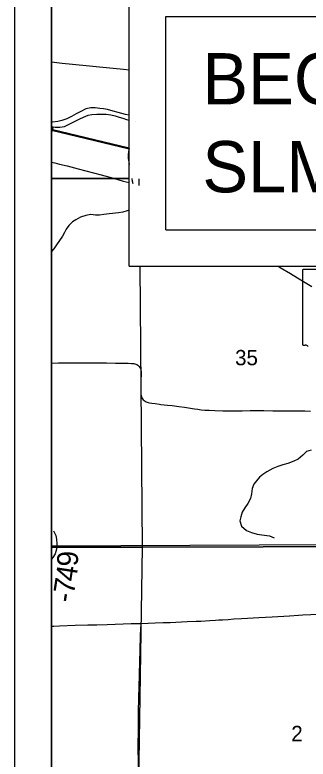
# Model space of a CAD drawing. Extents: x 0 to 34, y 0 to 22.
# Drawn here: x 1.76 to 2.561, y 16.14 to 18.172 of the extents above; entities that cross this region are included whole.
import ezdxf

# ---------------------------------------------------------------- set-up
doc = ezdxf.new("R2010")
doc.units = 0
for name, color, linetype in [('GM_X_County_Road', 7, 'Continuous'), ('GM_X_County_Road_Text', 7, 'Continuous'), ('GM_X_County_Text', 7, 'Continuous'), ('GM_X_Interchange_Ramps', 7, 'Continuous'), ('GM_X_Major_River_Text', 7, 'Continuous'), ('GM_X_State_Location', 7, 'Continuous'), ('GM_X_State_Route', 7, 'Continuous'), ('GM_X_State_Shield', 7, 'Continuous'), ('GM_X_Township_Road', 7, 'Continuous'), ('GM_X_Township_Text', 7, 'Continuous'), ('SH_Data', 7, 'Continuous'), ('SH_Text', 7, 'Continuous')]:
    doc.layers.add(name, color=color, linetype=linetype)

msp = doc.modelspace()

# ---------------------------------------------------------------- linework, layer by layer
at = {"layer": 'GM_X_County_Road'}
for p, q in [((2.6247, 17.4771), (2.5475, 17.4771)), ((2.5449, 17.4737), (2.5449, 17.2736))]:
    msp.add_line(p, q, dxfattribs=at)
for points in [[(1.8602, 17.7701), (1.8605, 17.77), (1.8696, 17.7677), (1.8816, 17.7646), (1.9027, 17.7595), (1.9328, 17.7516), (1.9748, 17.7406), (1.9958, 17.7349), (2.029, 17.7258), (2.0556, 17.7184), (2.0719, 17.7141)], [(2.4795, 17.4855), (2.4808, 17.4847), (2.4847, 17.4824), (2.5127, 17.4656), (2.5313, 17.4544), (2.5525, 17.4416), (2.5711, 17.4302)]]:
    msp.add_lwpolyline(points, dxfattribs=at)
for centre, radius, start, end in [((2.5479, 17.4741), 0.00305, 98.1301, 188.1301), ((2.5479, 17.2731), 0.00308, 171.9584, 258.3066), ((2.5484, 17.2936), 0.0235, 267.339, 280.6039), ((2.5532, 17.262), 0.00848, 29.7484, 93.2717)]:
    msp.add_arc(centre, radius, start, end, dxfattribs=at)
at = {"layer": 'GM_X_County_Road_Text'}
msp.add_line((2.0901, 17.8819), (2.0901, 17.8819), dxfattribs=at)
for points in [[(1.8644, 17.8663), (1.8622, 17.8575), (1.8602, 17.8514)], [(2.0719, 17.807), (2.0706, 17.7993), (2.0694, 17.7895), (2.0694, 17.78), (2.0709, 17.7705), (2.0719, 17.7633)], [(2.0792, 17.7249), (2.0807, 17.7177), (2.0826, 17.7112)], [(2.0719, 17.6391), (2.0666, 17.6368), (2.0548, 17.6334), (2.043, 17.6319), (2.0271, 17.63), (2.0172, 17.6285), (2.0032, 17.6266), (1.991, 17.6251), (1.98, 17.6255), (1.9675, 17.6266), (1.9542, 17.6243), (1.9394, 17.6198), (1.9269, 17.6126), (1.9174, 17.6069), (1.9079, 17.597), (1.9006, 17.5871), (1.8957, 17.5776), (1.8904, 17.5682), (1.8816, 17.5556), (1.874, 17.5442), (1.8664, 17.5336), (1.8602, 17.5259)], [(2.5688, 16.9838), (2.5559, 16.98), (2.546, 16.9698), (2.5338, 16.9591), (2.5213, 16.9535), (2.505, 16.947), (2.4917, 16.9436), (2.4776, 16.9387), (2.464, 16.9337), (2.4476, 16.9246), (2.4374, 16.9174), (2.4279, 16.9094), (2.4195, 16.9), (2.4123, 16.8905), (2.4077, 16.8791), (2.4062, 16.8643), (2.4031, 16.8514), (2.3963, 16.8381), (2.3883, 16.8263), (2.3803, 16.8142), (2.3769, 16.8016), (2.3746, 16.791), (2.3791, 16.7762), (2.392, 16.7644), (2.4057, 16.7583), (2.4212, 16.7538), (2.4345, 16.7522), (2.455, 16.7492), (2.4683, 16.7446)], [(1.8655, 16.7631), (1.8724, 16.7502), (1.8742, 16.7403), (1.8746, 16.7274), (1.8738, 16.713), (1.87, 16.7009), (1.8639, 16.6906), (1.8602, 16.6861)]]:
    msp.add_lwpolyline(points, dxfattribs=at)
at = {"layer": 'GM_X_County_Text'}
for p, q in [((1.8602, 17.8597), (2.0719, 17.8086)), ((1.8602, 17.8573), (2.0719, 17.8062))]:
    msp.add_line(p, q, dxfattribs=at)
at = {"layer": 'GM_X_Interchange_Ramps'}
for points in [[(1.8602, 17.2215), (1.8797, 17.2217), (1.8921, 17.2218), (1.9139, 17.222), (1.9356, 17.2221), (1.9667, 17.222), (1.9884, 17.222), (2.0101, 17.2217), (2.035, 17.2213), (2.0536, 17.2212), (2.0691, 17.2209), (2.0784, 17.2206), (2.0845, 17.22), (2.0875, 17.2194), (2.0903, 17.2185), (2.093, 17.2173), (2.0955, 17.2158), (2.0978, 17.2139), (2.0998, 17.2117), (2.1015, 17.2093), (2.1028, 17.2066), (2.1038, 17.2038), (2.1043, 17.2007), (2.1046, 17.1979), (2.1047, 17.1944), (2.1047, 17.1911), (2.1044, 17.1753), (2.1037, 17.1448), (2.1039, 17.139), (2.1039, 17.1358), (2.1046, 17.1325), (2.1054, 17.1288), (2.1068, 17.1264), (2.1084, 17.1236), (2.1104, 17.121), (2.1128, 17.1188), (2.1155, 17.1171), (2.1184, 17.1157), (2.1214, 17.1146), (2.1244, 17.1137), (2.1275, 17.113), (2.1337, 17.112), (2.1429, 17.1108), (2.1552, 17.1089), (2.159, 17.1084)], [(2.159, 17.1084), (2.1675, 17.1073), (2.1768, 17.1063), (2.1891, 17.1051), (2.2076, 17.1029), (2.223, 17.1009), (2.2506, 17.0965), (2.2598, 17.0952), (2.269, 17.094), (2.2783, 17.0931), (2.2907, 17.0923), (2.3062, 17.0918), (2.3279, 17.0912), (2.3434, 17.0908), (2.3527, 17.0906), (2.3652, 17.0908), (2.3807, 17.0911), (2.4024, 17.0916), (2.4148, 17.0918), (2.4397, 17.0916), (2.4645, 17.0912), (2.4894, 17.0912), (2.5049, 17.0912), (2.5359, 17.0909), (2.5514, 17.0907), (2.5669, 17.0902)], [(2.0973, 16.1065), (2.0974, 16.1168), (2.0972, 16.1385), (2.0969, 16.1634), (2.0969, 16.1852), (2.0972, 16.2101), (2.0976, 16.2381), (2.0979, 16.263), (2.0988, 16.3128), (2.0993, 16.3315), (2.0995, 16.3439), (2.1, 16.3625), (2.1006, 16.381), (2.1012, 16.3965), (2.1017, 16.4121), (2.1021, 16.4308), (2.1024, 16.4463), (2.1028, 16.468), (2.1031, 16.4804), (2.1037, 16.4929), (2.1045, 16.5107)]]:
    msp.add_lwpolyline(points, dxfattribs=at)
at = {"layer": 'GM_X_State_Route'}
msp.add_line((2.0999, 17.7064), (2.0998, 17.7248), dxfattribs=at)
for points in [[(2.0795, 18.2679), (2.0616, 18.746), (1.8602, 18.7459), (1.8602, 17.7252), (2.0719, 17.7249)], [(2.0719, 17.7249), (1.8602, 17.7252), (1.8602, 16.7185), (2.1086, 16.7183), (2.1019, 17.4855)], [(3.0896, 17.4855), (3.0962, 16.7214), (2.1086, 16.7183), (2.1019, 17.4855)], [(4.1201, 16.507), (4.1149, 16.7255), (3.8667, 16.7261), (3.8624, 16.726), (3.8538, 16.7259), (3.7775, 16.7251), (3.6944, 16.7259), (3.6091, 16.7254), (3.5492, 16.7252), (3.5064, 16.7242), (3.4642, 16.7247), (3.3781, 16.7258), (3.3363, 16.7271), (3.2929, 16.7282), (3.2508, 16.7281), (3.0563, 16.7255), (2.994, 16.7266), (1.8602, 16.7212), (1.8602, 14.3866), (4.1451, 14.3866)]]:
    msp.add_lwpolyline(points, dxfattribs=at)
for points in [[(1.8602, 16.7185), (1.8602, 15.723), (2.0927, 15.7254), (2.1086, 16.7183)], [(2.1086, 16.7183), (3.0962, 16.7214), (3.1048, 15.7312), (2.0927, 15.7254)]]:
    msp.add_lwpolyline(points, close=True, dxfattribs=at)
at = {"layer": 'GM_X_State_Shield'}
for points in [[(2.0289, 17.9091), (2.0126, 17.9133), (2.0024, 17.9152), (1.9921, 17.9163), (1.9796, 17.9178), (1.9671, 17.9179), (1.9538, 17.9152), (1.9401, 17.9084), (1.9272, 17.9015), (1.915, 17.8947), (1.9021, 17.8883), (1.8881, 17.8837), (1.8774, 17.8811), (1.8638, 17.8795), (1.8602, 17.8797)], [(2.0719, 17.8978), (2.0623, 17.9003), (2.0525, 17.903), (2.0422, 17.9053), (2.0289, 17.9091)], [(1.8602, 17.8669), (1.8698, 17.8655), (1.8827, 17.8651), (1.896, 17.8674), (1.9063, 17.8727), (1.9283, 17.8837), (1.9378, 17.8882), (1.9477, 17.8928), (1.9602, 17.8981), (1.9701, 17.8996), (1.9838, 17.9008), (1.9948, 17.9011), (2.0092, 17.9011), (2.0225, 17.8992), (2.0342, 17.8962), (2.0445, 17.8931), (2.0551, 17.8901), (2.065, 17.8867), (2.0719, 17.8849)]]:
    msp.add_lwpolyline(points, dxfattribs=at)
at = {"layer": 'GM_X_Township_Road'}
for points in [[(2.0719, 18.0211), (2.0566, 18.0227), (1.9916, 18.0292), (1.9545, 18.0328), (1.8897, 18.0396), (1.8602, 18.0427)], [(2.1045, 16.5107), (2.1433, 16.5122), (2.1651, 16.5128), (2.1838, 16.5134), (2.1993, 16.514), (2.2303, 16.5153), (2.2552, 16.5166), (2.2676, 16.5171), (2.2924, 16.5186), (2.3079, 16.5195), (2.3172, 16.52), (2.3265, 16.5207), (2.342, 16.5216), (2.3575, 16.5226), (2.3792, 16.524), (2.3947, 16.525), (2.4258, 16.5267), (2.4629, 16.5288), (2.5094, 16.5316), (2.5341, 16.533), (2.5465, 16.5337), (2.5681, 16.5346), (2.5984, 16.536)], [(1.8602, 16.503), (1.8661, 16.5033), (1.8816, 16.5039), (1.9251, 16.5054), (1.9593, 16.5062), (1.9841, 16.5068), (2.0121, 16.5075), (2.0556, 16.509), (2.0773, 16.5099), (2.1045, 16.5107)]]:
    msp.add_lwpolyline(points, dxfattribs=at)
at = {"layer": 'SH_Data'}
for points in [[(1.7602, 21.2866), (8.7602, 21.2866), (8.7602, 14.2866), (1.7602, 14.2866)], [(1.8602, 21.1866), (8.6602, 21.1866), (8.6602, 14.3866), (1.8602, 14.3866)]]:
    msp.add_lwpolyline(points, close=True, dxfattribs=at)
at = {"layer": 'SH_Text'}
for p, q in [((2.0719, 17.4855), (2.0719, 18.2679)), ((2.1719, 17.5855), (2.1719, 18.1679)), ((2.1719, 18.1679), (4.3056, 18.1679)), ((2.1719, 17.5855), (4.3056, 17.5855)), ((2.0719, 17.4855), (4.0477, 17.4855))]:
    msp.add_line(p, q, dxfattribs=at)

# ---------------------------------------------------------------- texts
at = {"layer": 'GM_X_Major_River_Text'}
for s in ['s', 'r']:
    msp.add_text(s, height=0.000189, dxfattribs=at).set_placement((2.2828, 17.5877))
msp.add_text('39', height=0.000189, rotation=0, dxfattribs=at).set_placement((2.2351, 17.5739))
at = {"layer": 'GM_X_State_Location'}
for s, height, p in [('35', 0.04186, (2.3613, 17.2153)), ('2', 0.0419, (2.5147, 16.189))]:
    msp.add_text(s, height=height, rotation=0, dxfattribs=at).set_placement(p)
at = {"layer": 'GM_X_Township_Text'}
for s, rotation, p in [('9', 89.8094, (1.9325, 16.666)), ('4', 81.5111, (1.9267, 16.6227)), ('7', 81.1412, (1.9213, 16.588)), ('-', 81.2198, (1.9178, 16.5652))]:
    msp.add_text(s, height=0.0568, rotation=rotation, dxfattribs=at).set_placement(p)
at = {"layer": 'SH_Text'}
for s, p in [('BEGIN ACQUISITION', (2.2719, 17.9275)), ('SLM 0.70', (2.2719, 17.6875))]:
    msp.add_text(s, height=0.14, dxfattribs=at).set_placement(p)

doc.saveas('drawing.dxf')
